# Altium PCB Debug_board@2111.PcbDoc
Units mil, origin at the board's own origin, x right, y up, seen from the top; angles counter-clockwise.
Board outline 1771.65 x 984.25 mil, 2 copper layers (Top Layer, Bottom Layer); 26 components, 28 nets, 104 pads, 124 vias.
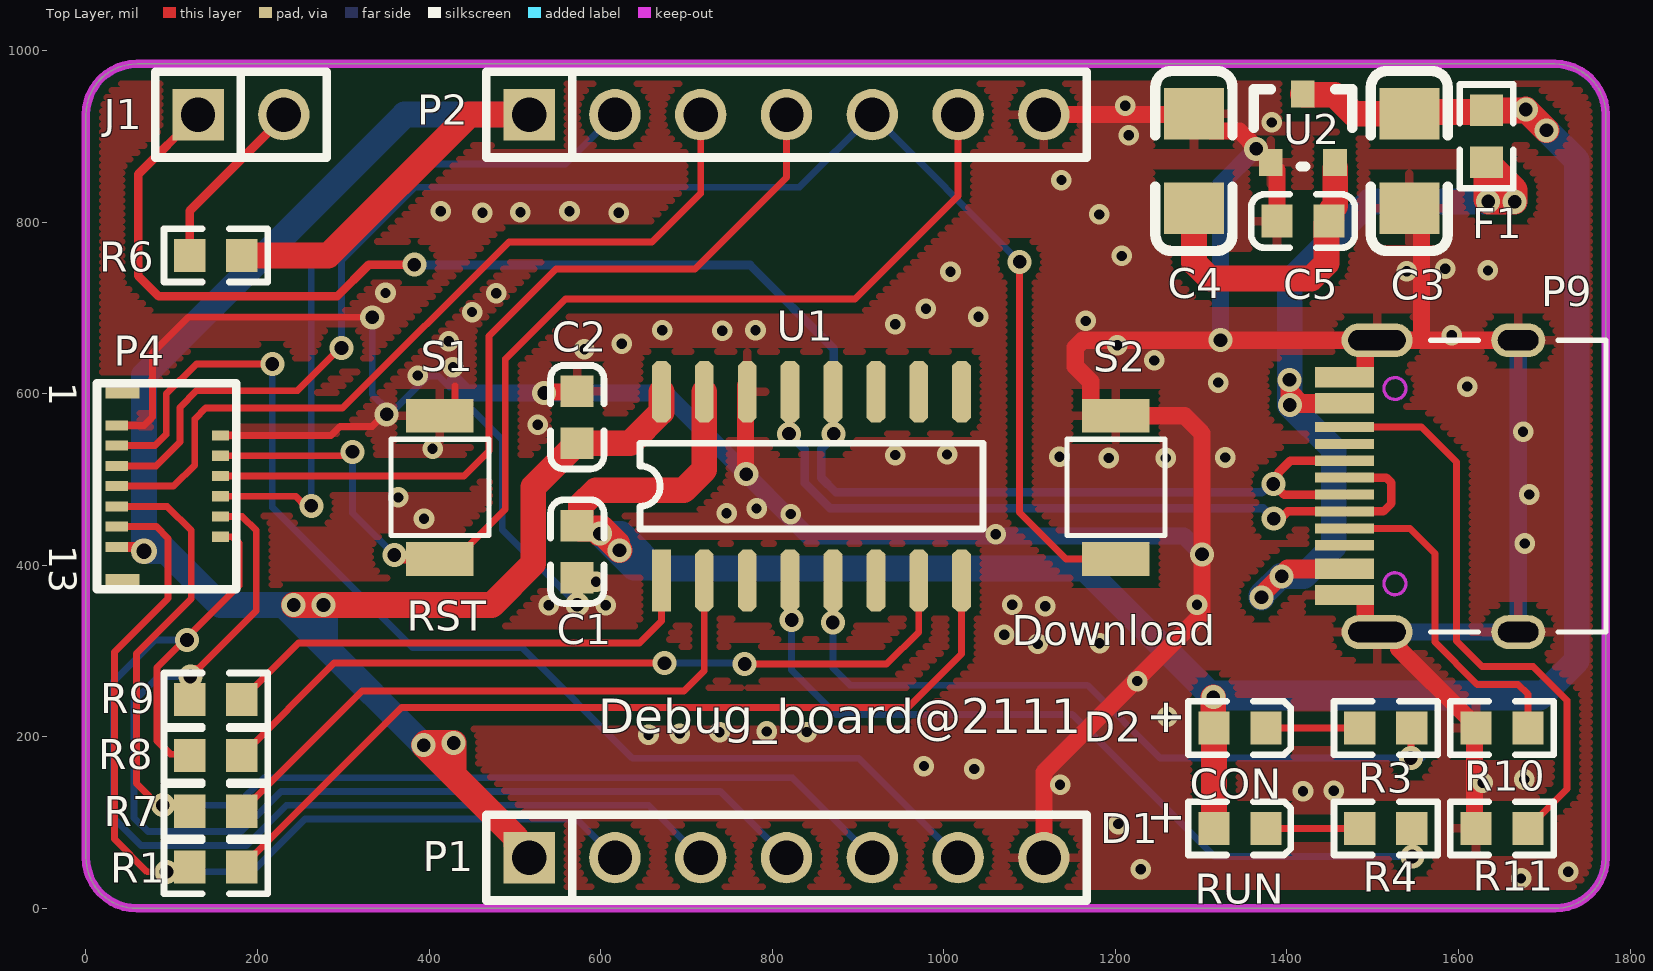
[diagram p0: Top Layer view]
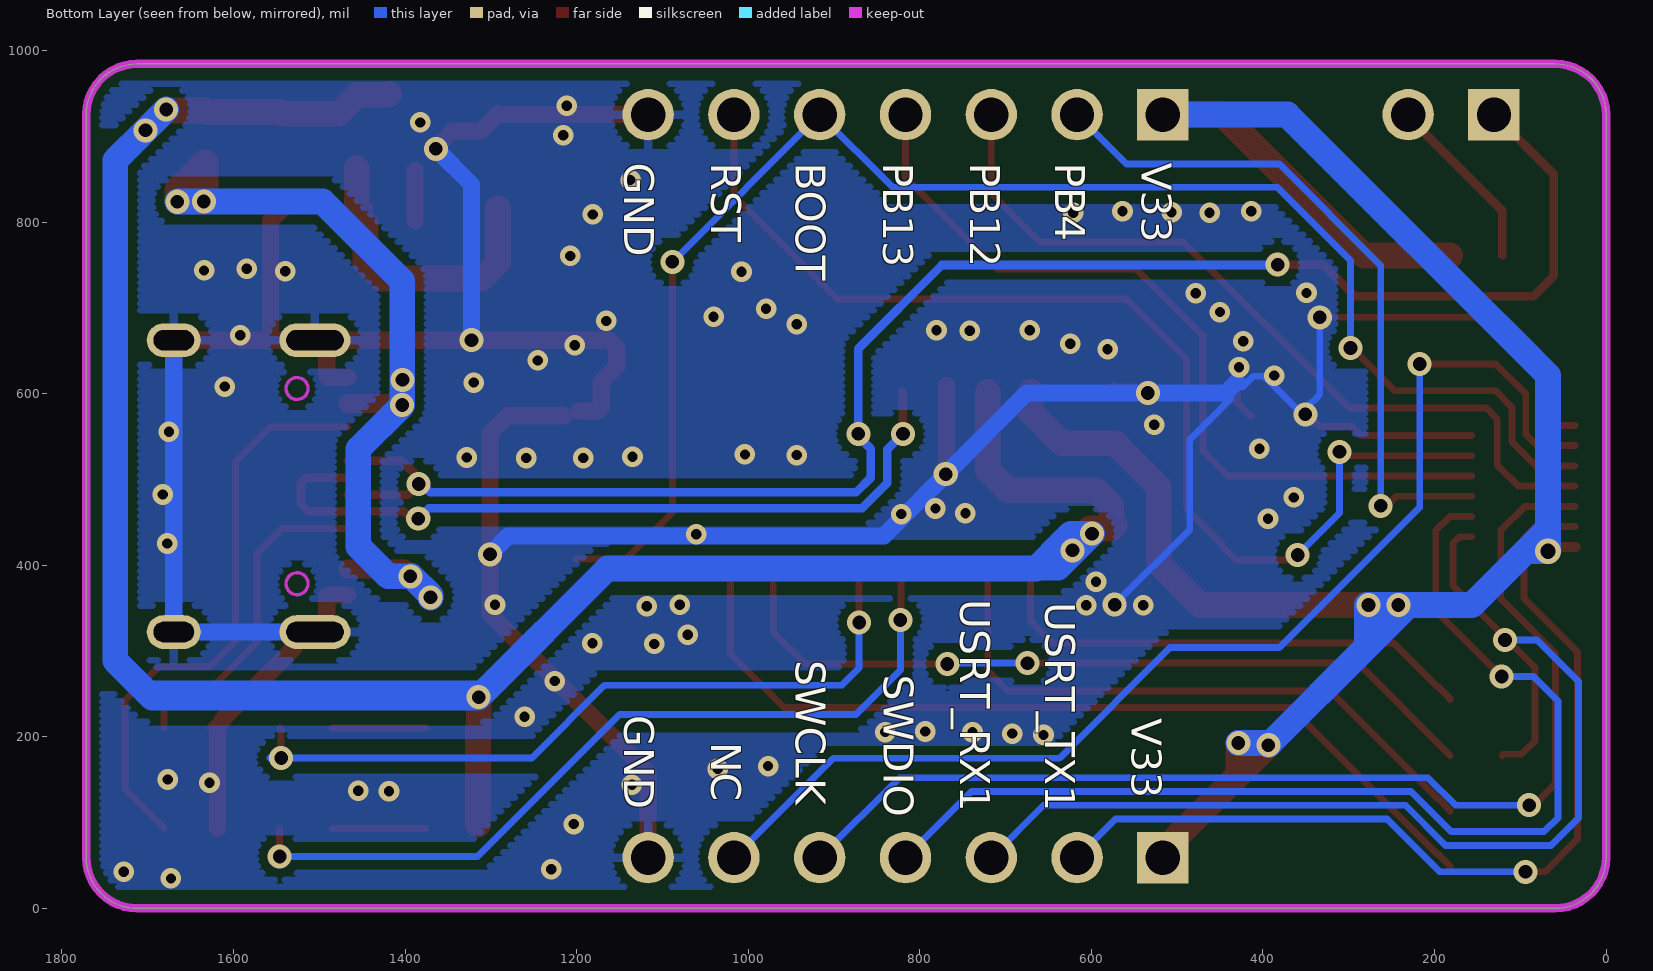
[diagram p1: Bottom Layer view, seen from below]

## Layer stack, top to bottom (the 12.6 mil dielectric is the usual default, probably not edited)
Top Solder: solder mask 0.4, Solder Resist, Dk 3.5
Top Layer: signal copper 1.4
Dielectric 1: dielectric 12.6, FR-4, Dk 4.8
Bottom Layer: signal copper 1.4
Bottom Solder: solder mask 0.4, Solder Resist, Dk 3.5

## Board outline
0,59.06 0,925.2 cw(c59.06,925.2) 59.06,984.25 1712.6,984.25 cw(c1712.6,925.2) 1771.65,925.2 1771.65,59.06 cw(c1712.6,59.06) 1712.6,0 59.06,0 cw(c59.06,59.06)

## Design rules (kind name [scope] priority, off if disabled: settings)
Clearance Clearance_2 [InComponent('P9')] p1: gap=6 ignorepadtopadclearanceinfootprint=FALSE
Clearance Clearance_1 [InPolygon] p2: gap=10 ignorepadtopadclearanceinfootprint=FALSE
Clearance [All] p3: gap=8 ignorepadtopadclearanceinfootprint=FALSE
ComponentClearance [All] p1 off: gap=10 collisioncheckmode=3 verticalgap=10 showdistances=FALSE
DiffPairsRouting [All] p1: maxlimit=10 minlimit=7 mostfreqgap=8 toplayer_minwidth=6 toplayer_maxwidth=15 toplayer_prefwidth=8 bottomlayer_minwidth=6 bottomlayer_maxwidth=15 bottomlayer_prefwidth=8 maxuncoupledlength=500
MinimumSolderMaskSliver [All] p1 off: minsoldermaskwidth=10
PolygonConnect PolygonConnect_1 [IsVia] p1: connectstyle=Direct reliefconductorwidth=10 reliefentries=4 polygonreliefangle="90 Angle" airgapwidth=10
PolygonConnect [All] p2: connectstyle=Relief reliefconductorwidth=10 reliefentries=4 polygonreliefangle="90 Angle" airgapwidth=10
RoutingVias [All] p1: holewidth=16 width=28 viastyle="Through Hole" minholewidth=12 minwidth=24 maxholewidth=28 maxwidth=50
SilkToSilkClearance [All] p1 off: silktosilkclearance=10
SilkToSolderMaskClearance [IsPad] p1 off: minsilkscreentomaskgap=10 clearancetoexposedcopper=TRUE
SolderMaskExpansion [All] p1: expansion=4 istentingtop=FALSE
Width [All] p1: maxlimit=100 minlimit=6 preferedwidth=10
25 further rules are at their usual default settings.

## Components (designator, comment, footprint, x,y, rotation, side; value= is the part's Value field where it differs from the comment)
C1 "0.1uF" 0603_C 572.65,446.13 r270 top
C2 "0.1uF" 0603_C 572.65,542.13 r90 top
C3 "10uF" 3216_C 1542.65,926.13 r90 top
C4 "10uF" 3216_C 1291.65,816.13 r270 top
C5 "0.1uF" 0603_C 1449.07,801.13 r180 top
D1 "RED" 0603+ 1315.02,93.13 r0 top
D2 "BLUE" 0603+ 1315.02,210.13 r0 top
F1 "500mA" 0603 1632.65,869.5 r90 top
J1 "Header 2" SIP2-2.54MM 130.65,925.2 r90 top
P1 "Header 7" SIP7-2.54mm 516.65,59.06 r90 top
P2 "Header 7" SIP7-2.54mm 516.65,925.2 r90 top
P4 "FPC连接器 13PIN_0.3mm" FFC/FPC-13(6+7)-P0.3 35.98,492.13 r270 top
P9 "TYPE-C" TYPE-C-Receptacle-2.0 1466.9,492.13 r90 top
R1 "270" 0603 121.07,48.05 r0 top
R3 "1K" 0603 1545.65,210.13 r180 top
R4 "1K" 0603 1545.65,93.13 r180 top
R6 "4.7K" 0603 121.07,761.04 r0 top
R7 "270" 0603 121.07,113.12 r0 top
R8 "270" 0603 121.07,178.2 r0 top
R9 "270" 0603 121.07,243.27 r0 top
R10 "NC(5.1K)" 0603 1681.08,210.13 r180 top
R11 "NC(5.1K)" 0603 1681.08,93.13 r180 top
S1 "RST" 贴片按键 412.65,407.13 r90 top
S2 "Download" 贴片按键 1200.65,407.13 r90 top
U1 "CH549G" SOP16 670.83,382.13 r0 top
U2 "CE6219" SOT-23 1381.25,869.6 r0 top

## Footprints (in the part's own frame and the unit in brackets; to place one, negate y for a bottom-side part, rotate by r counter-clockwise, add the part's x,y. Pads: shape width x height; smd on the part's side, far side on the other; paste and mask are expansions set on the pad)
0603 [mm]
  rect 0.93x0.98 smd: 1(0,0) 2(1.54,0)
  silkscreen extent -0.76,-0.79 2.3,0.79
0603+ [mm]
  rect 0.93x0.98 smd: 1(0,0) 2(1.54,0)
  silkscreen extent -0.76,-0.79 2.27,0.79
0603_C [mm]
  rect 0.93x0.98 smd: 1(0,0) 2(1.54,0)
  silkscreen extent -0.76,-0.79 2.31,0.79
3216_C [mil]
  rect 60x70 smd: 1(0,0) 2(-110,0)
  silkscreen extent -160,-45 50,45
FFC/FPC-13(6+7)-P0.3 [mm]
  rect 0.35x1 smd mask+0.102: 0(-2.775,0.165) 0(2.775,0.165)
  rect 0.3x0.67 smd mask+0.102: 1(-1.8,0) 3(-1.2,0) 5(-0.6,0) 7(0,0) 9(0.6,0) 11(1.2,0) 13(1.8,0)
  rect 0.3x0.5 smd mask+0.102: 2(-1.5,3.065) 4(-0.9,3.065) 6(-0.3,3.065) 8(0.3,3.065) 10(0.9,3.065) 12(1.5,3.065)
  silkscreen extent -3.05,-0.59 3.05,3.53
SIP2-2.54MM [mil]
  rect 60x60 hole 40: 1(0,0)
  round 60 hole 40: 2(0,-100)
  silkscreen extent -50,-150 50,50
SIP7-2.54mm [mil]
  rect 60x60 hole 40: 1(0,0)
  round 60 hole 40: 2(0,-100) 3(0,-200) 4(0,-300) 5(0,-400) 6(0,-500) 7(0,-600)
  silkscreen extent -50,-650 50,50
SOP16 [mil]
  rect 22x72 smd: 1(0,0)
  oct 22x72 smd: 2(50,0) 3(100,0) 4(150,0) 5(200,0) 6(250,0) 7(300,0) 8(350,0) 9(350,220) 10(300,220) 11(250,220) 12(200,220) 13(150,220) 14(100,220) 15(50,220) 16(0,220)
  silkscreen extent -25,60 375,160
SOT-23 [mm]
  rect 0.7x0.8 smd: 1(0,0) 2(1.9,0) 3(0.95,2.02)
  silkscreen extent -0.51,-0.13 2.41,2.16
TYPE-C-Receptacle-2.0 [mm]
  oval 1x1.6 hole 0.6 slot 1.2 at 90 deg: 0(-4.32,-5.15) 0(4.32,-5.15)
  oval 1x2.1 hole 0.6 slot 1.7 at 90 deg: 0(-4.32,-0.97) 0(4.32,-0.97)
  rect 0.6x1.75 smd: A1(-3.225,0) A4(-2.45,0) B1(3.225,0) B4(2.45,0)
  rect 0.3x1.75 smd: A5(-1.25,0) A6(-0.25,0) A7(0.25,0) A8(1.25,0) B5(1.75,0) B6(0.75,0) B7(-0.75,0) B8(-1.75,0)
  Keep-Out Layer circle w0.1: c-2.89,-1.5 r0.325
  Keep-Out Layer circle w0.1: c2.89,-1.5 r0.325
  silkscreen extent -4.32,-7.75 4.32,-2.55
贴片按键 [mm]
  rect 1x2 smd: 1(0,0) 2(4.242,0)
  silkscreen extent 0.69,-1.45 3.55,1.45

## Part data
C1 C2: library part C0603, "Capacitor"
C3 C4 C5: library part CAP, "Capacitor"
D1 D2: library part D0603, "Typical RED, GREEN, YELLOW, AMBER GaAs LED"
F1: library part FUSE1, "Fuse"
J1: "Header, 2-Pin"
P1 P2: "Header, 7-Pin"
P4: library part "Header 13", "Header, 13-Pin"
P9: library part TYPE-C1
R1 R3 R4 R6 R7 R8 R9: library part R0603, "Resistor"
R10 R11: library part Res2, "Resistor"
S1 S2: library part SW-PB, "Switch"
U1: "8bit MCS51 MCU with ADC & USB type-C host & device & dual UART & SPI"
U2: library part LM1117_3.3V

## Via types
v1: diameter 24, hole 12, Top Layer to Bottom Layer, tented both sides, 79 vias
v2: diameter 28, hole 16, Top Layer to Bottom Layer, tented both sides, 44 vias
v3: diameter 30, hole 18, Top Layer to Bottom Layer, tented both sides, 1 vias

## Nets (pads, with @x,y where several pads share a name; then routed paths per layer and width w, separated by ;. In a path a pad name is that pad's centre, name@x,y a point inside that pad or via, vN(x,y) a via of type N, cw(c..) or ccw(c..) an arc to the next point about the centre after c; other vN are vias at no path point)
3V3: C4.1 C5.1 U2.2 | length 348.6
  Top Layer w30: C4.1 1291.65,752.77 1310.34,734.08 1428.36,734.08 1446.12,751.83 1446.12,798.17 C5.1 1452.37,804.43 1452.37,814.6 1456.37,818.6 U2.2@1456.37,863.26
5V: C1.1 C3.1 D1.1 D2.1 F1.2 U1.15 U2.3 | length 3194.1
  Top Layer w30: v2(599.33,436.63) 602.68,436.63 v2@619.2,420.1 ; v2(622.02,417.29) v2@619.2,420.1 ; U1.15 720.83,511.14 697.02,487.33 594.61,487.33 576.94,469.67 576.94,449.43 C1.1@573.64,446.13 ; v2(1314.14,246.11) 1314.14,211.01 D2.1 D1.1@1315.02,97.45 ; U2.3 1419.4,948.38 1455.4,948.38 1477.65,926.13 C3.1 1544.65,928.13 1630.65,928.13 F1.2 v2@1677.39,930.13 ; v2(1678.5,931.24) v2@1677.39,930.13 ; v2(1702.56,906.91) 1679.35,930.13 v2@1677.39,930.13 ; C1.1@573.64,446.13 C1.1@576.94,442.82 ; C1.1@573.64,446.13 C1.1 575.96,442.82 C1.1@576.94,442.82 ; C1.1@576.94,442.82 601.63,442.82 619.2,425.25 v2@619.2,420.1
  Bottom Layer w30: 664.34,396.14 1164.11,396.14 1309.54,250.71 1314.14,250.71 1699.93,250.71 ; v2(1314.14,246.11) 1314.76,245.49 1694.71,245.49 1699.93,250.71 ; v2(1678.5,931.24) 1702.7,907.04 1737.76,871.97 1737.76,288.54 1699.93,250.71 ; v2(599.33,436.63) 620.35,415.62 638.69,397.27 663.2,397.27 632.6,427.87 623.84,436.63 v2(599.33,436.63)
5V_USB: F1.1 P9.A4 P9.B4 | length 1125.6
  Top Layer w22: v2(1370.27,362.42) 1370.27,365.2 v2@1400.74,395.67 ; v2(1393.86,387.02) 1393.86,388.79 v2@1400.74,395.67 ; v2(1403.05,616.08) 1403.23,615.89 1403.23,601.34 ; 1427.42,588.28 v2@1416.29,588.28 ; P9.A4 v2@1400.74,395.67 ; P9.B4@1466.9,588.28 v2@1416.29,588.28 ; 1403.23,601.34 1403.23,586.78 v2(1403.42,586.59) 1405.05,586.59 1406.74,588.28 v2@1416.29,588.28 ; 1403.23,601.34 v2@1416.29,588.28
  Top Layer w30: v2@1632.65,825.82 F1.1 1633.64,869.5 1665.52,837.61 v2(1665.52,823.61) 1665.33,823.81 v2(1634.66,823.81) v2@1632.65,825.82
  Bottom Layer w30: v2(1370.27,362.42) 1370.27,364.94 v2@1393.1,387.78 ; v2(1393.86,387.02) 1419.77,387.02 1454.6,421.85 1454.6,535.41 v2(1403.42,586.59) 1403.42,616.08 1403.42,731.26 1495.97,823.81 v2(1634.66,823.81) 1665.33,823.81 v2(1665.52,823.61)
BOOT: P2.5 P4.5 S2.1 | length 1803.5
  Top Layer w8: P4.5 81.94,515.75 109.62,543.43 109.62,583.86 129.07,603.31 246.41,603.31 296.2,653.1 v2(298.01,653.1) ; v2(1088.44,753.65) 1088.44,461.32 1142.63,407.13 S2.1
  Bottom Layer w8: v2(298.01,653.1) 298.01,755.12 383.44,840.55 832.01,840.55 P2.5 v2@1088.32,753.53
D_SWCLK: R7.2 U1.2 | length 712.8
  Top Layer w8: R7.2 181.7,114.11 196.01,128.42 196.99,128.42 321.97,253.39 697.3,253.39 720.83,276.91 U1.2
D_SWDIO: R9.2 U1.1 | length 574.9
  Top Layer w8: R9.2 181.7,244.26 196.01,258.57 196.99,258.57 247.75,309.32 645.34,309.32 670.83,334.8 U1.1
GND: C1.2 C2.2 C3.2 C4.2 C5.2 P1.7 P2.7 P4.1 P4.2 P9.0 P9.A1 P9.B1 R10.2 R11.2 S1.2 S2.2 U1.14 U2.1 | length 5194.2
  Top Layer w8: P4.1 67.95,562.99 77.43,572.48 77.43,647.21 119.18,688.96 v2(333.73,688.96) ; P4.2 285.74,551.18 296.12,561.56 333.68,561.56 347.88,575.77 v2(350.58,575.77) ; S1.2 414.46,574.13 430.15,589.81 430.15,609.13
  Top Layer w20: v2(534.23,600.56) 535.33,601.66 571.56,601.66 C2.2 ; U1.14@768.84,609.25 768.84,506.93 v2(769.73,506.03) ; P1.7 1116.65,158.35 1301.09,342.79 v2(1301.09,412.68) 1301.09,553.6 1280.57,574.13 S2.2@1214.81,574.13 ; P2.7 1290.72,925.2 C4.2 1311.65,906.13 1344.72,906.13 v2@1364.84,886.01 ; S2.2@1197.87,579.63 1175.46,579.63 1171.28,583.81 1171.28,613.81 1153.23,631.86 1153.23,653.42 1162.02,662.2 v2(1322.6,662.2) 1505.09,662.2 P9.0@1669.65,662.2 ; C5.2 U2.1@1388.44,860.44 ; P9.A1 1489.54,365.16 1491.35,363.35 1491.35,330.83 1500.13,322.05 P9.0@1505.09,322.05 ; P9.B1 1489.54,619.09 1491.35,620.91 1491.35,653.26 1486.88,657.72 P9.0@1484.2,657.72 ; P9.0@1510.89,322.05 1521.5,322.05 1530.45,313.1 1530.45,302.49 1612.14,220.8 1612.14,218.43 R10.2 ; C3.2 1556.9,801.88 1556.9,662.21 ; R11.2@1618.65,93.13 R10.2@1618.65,208.13
  Bottom Layer w8: v2(333.73,688.96) 333.73,599.17 350.58,582.32 v2(350.58,575.77) 354.39,575.77 356.42,577.8 393.13,614.51 398.82,620.2 411.32,620.2 423.79,607.74 ; 437.32,594.2 485.25,546.27 485.25,441.48 v2(572.79,353.95)
  Bottom Layer w20: 430.15,614.09 438.4,605.84 443.68,600.56 v2(534.23,600.56) 675.2,600.56 v2(769.73,506.03) v1@818.94,456.83 ; v1@820.32,458.21 821.85,458.21 822.39,457.67 822.39,453.37 841.66,434.11 1279.67,434.11 v2(1301.09,412.68) ; v2(1322.6,662.2) 1322.6,843.77 v2(1364.15,885.32) ; P9.0@1505.09,322.05 1669.65,322.05 P9.0@1669.65,662.2
  other v1: 1673,34.82 1727.96,42.45 1229.44,45.51 1203.48,98.19 1418.77,136.36 1454.65,137.12 1135.54,143.99 1627.95,146.28 1676.81,150.1 1035.53,162.31 976.86,165.74 655.78,202.1 692.23,203.67 738.55,205.06 840.37,205.42 793.73,206.08 1260.68,223.41 1225.52,264.84 1109.38,308.16 1181.57,308.79 1070.46,318.83 1118.17,352.11 539.36,353.19 605.94,353.19 1079.87,353.99 1295.2,353.99 594.61,380.73 1677.11,425.27 1060.66,436.11 394.08,454.02 821.62,459.52 746.8,460.61 781.75,466.07 364.17,478.95 1682.54,482.32 1192.14,524.86 1258.76,524.86 1328.04,525.53 1134.85,526.19 943.48,528.31 1003.82,529.1 404.09,535.61 1675.3,555.66 526.75,563.79 1610.1,608.18 1319.98,612.86 386.67,620.97 427.88,630.8 1245.37,638.65 581.07,651.7 1202.38,656.21 624.66,658.13 422.8,660.94 1591.99,667.94 741.87,673.14 671.83,673.86 780.47,673.86 943.48,680.77 1165.43,684.68 1040.35,689.5 450.08,695 979.21,699.03 349.24,717.35 478.4,716.84 1007.79,741.91 1539.65,742.67 1634.34,743.57 1584.74,745.38 1207.54,760.48 1181.25,808.85 462.16,810.84 506.46,811.38 620.98,810.84 413.54,812.46 563.72,812.46 1137.11,848.91 1215.58,901.22 1382.24,916.08 1211.49,935.55
LED_CON: R3.1 U1.5 | length 868.3
  Top Layer w8: v2(870.65,333.13) 870.83,333.3 U1.5 ; v2(1544.47,175.15) 1544.47,208.94 R3.1
  Bottom Layer w8: v2(870.65,333.13) 870.65,279.9 890.51,260.04 1167.26,260.04 1252.15,175.15 v2(1544.47,175.15) v2@1557.79,175.15
LED_RUN: R4.1 U1.4 | length 951.5
  Top Layer w8: U1.4 821.72,381.23 821.72,336.99 v2(822.62,336.09) ; R4.1 1546.19,92.59 v2(1546.19,60.45)
  Bottom Layer w8: v2(822.62,336.09) 822.62,277.88 874.47,226.03 1149.83,226.03 1315.42,60.45 v2(1546.19,60.45)
NC: P1.6 P4.3 | length 1384
  Top Layer w8: P4.3 80.57,539.37 93.55,552.35 93.55,599.37 128.74,634.56 v2(217.23,634.56)
  Bottom Layer w8: v2(217.23,634.56) 217.23,467.32 380.59,303.96 508.21,303.96 637.34,174.83 900.88,174.83 P1.6
NetD1_2: D1.2 R4.2 | length 109.4
  Top Layer w8: D1.2 R4.2
NetD2_2: D2.2 R3.2 | length 109.4
  Top Layer w8: D2.2 R3.2
NetJ1_2: J1.2 R6.1 | length 209.5
  Top Layer w10: R6.1 121.07,813.2 144.92,837.05 230.65,922.78 J1.2
NetP9_A5: P9.A5 R10.1 | length 394.2
  Top Layer w8: P9.A5 1543.31,442.91 1572.54,413.68 1572.54,310.32 1621.83,261.03 1669.56,261.03 1681.08,249.52 R10.1
NetP9_B5: P9.B5 R11.1 | length 682
  Top Layer w8: P9.B5 1556.98,561.02 1597.6,520.41 1597.6,311.72 1627.58,281.74 1687.14,281.74 1726.43,242.45 1726.43,139.2 1695.65,108.42 1695.38,108.42 1681.08,94.11 R11.1
PB4: P2.2 P4.8 | length 817.7
  Top Layer w8: P4.8 244.38,480.32 255.57,469.13 v2(262.65,469.13)
  Bottom Layer w8: v2(262.65,469.13) 262.65,749.43 380.78,867.56 559.02,867.56 P2.2
PB12: P2.3 P4.7 | length 945.1
  Top Layer w8: P4.7 102.07,492.13 126.89,516.95 126.89,570.34 139.57,583.01 299.11,583.01 492.94,776.85 660.06,776.85 716.65,833.45 P2.3
PB13: P2.4 P4.6 | length 956
  Top Layer w8: P4.6 329.41,503.94 440.74,503.94 457.93,521.13 469.86,533.05 469.86,667.04 547.99,745.18 710.06,745.18 816.65,851.77 P2.4
RST: P2.6 P4.4 S1.1 | length 1329.8
  Top Layer w8: P4.4 306.09,527.56 v2(310.65,532.13) ; v2(359.5,411.77) 365.07,406.19 431.41,406.19 448.02,422.81 448.02,424.59 488.79,465.36 488.79,640.15 558.96,710.32 896.48,710.32 1016.65,830.49 P2.6
  Bottom Layer w8: v2(310.65,532.13) 310.65,460.61 v2(359.5,411.77)
SWCLK: P1.5 P4.9 R7.1 | length 1342.1
  Top Layer w8: P4.9 94.73,468.5 122.78,440.46 122.78,361.18 58.79,297.2 58.79,145.25 v2@89.36,114.69
  Bottom Layer w8: v2(89.65,120.13) 175.59,120.13 207.56,152.1 823.61,152.1 P1.5
SWDIO: P1.4 P4.10 R9.1 | length 1279.7
  Top Layer w8: v2@121.07,279.64 131.17,279.64 198.52,346.99 198.52,440.33 182.16,456.69 P4.10
  Bottom Layer w8: v2(121.65,270.13) 84.36,270.13 56.03,241.79 56.03,105.43 72.17,89.29 180.49,89.29 227.3,136.1 739.61,136.1 P1.4
UART0_RX: R8.2 U1.7 | length 909.4
  Top Layer w8: R8.2 289.24,285.73 v2(674.41,285.73) ; v2(767.87,284.84) 933.43,284.84 970.83,322.24 U1.7
  Bottom Layer w8: v2(674.41,285.73) 766.98,285.73 v2(767.87,284.84)
UART0_TX: R1.2 U1.8 | length 1028.3
  Top Layer w8: R1.2 181.7,49.03 196.01,63.34 196.99,63.34 367.67,234.01 958.38,234.01 1020.83,296.46 U1.8
UART_RX1: P1.3 P4.12 R8.1 | length 1347.3
  Top Layer w8: R8.1 119.65,179.62 98.28,179.62 82.81,195.09 82.81,280.51 178.3,376.01 178.3,425.82 171.06,433.07 P4.12
  Bottom Layer w8: v2(117.92,312.64) 80.63,312.64 32.24,264.24 32.24,105.2 64.14,73.29 187.12,73.29 233.93,120.1 655.61,120.1 P1.3
UART_TX1: P1.2 P4.11 R1.1 | length 1085.1
  Top Layer w8: P4.11 82.1,444.88 95.85,431.13 95.85,361.33 33.44,298.93 33.44,80.56 71.44,42.56 v2(93.9,42.56)
  Bottom Layer w8: v2(93.9,42.56) 193.72,42.56 255.26,104.1 571.61,104.1 P1.2
USB_N: P9.A7 P9.B7 U1.13 | length 909.4
  Top Layer w10: v2(819.65,553.13) 819.65,600.95 U1.13 ; v2@1380.06,453.43 1380.75,454.13 v2(1384.65,454.13) 1392.44,454.13 1400.91,462.6 P9.B7 1512.5,462.6 1521.86,471.96 1521.86,496.11 1516,501.97 P9.A7
  Bottom Layer w10: v2(819.65,553.13) 837.94,534.84 837.94,495.7 867.07,466.57 1372.21,466.57 v2(1384.65,454.13)
USB_P: J1.1 P9.A6 P9.B6 U1.12 | length 1973.5
  Top Layer w10: J1.1 61.06,855.6 61.06,737.15 84.91,713.31 292.73,713.31 329.67,750.25 v2(382.84,750.25) ; v2(1384.1,494.53) 1384.1,499.4 1389.86,505.16 1389.86,507.7 1403.82,521.65 P9.B6 ; v2@1390.44,496.49 1390.44,488.18 1396.79,481.84 1466.45,481.84 P9.A6
  Bottom Layer w10: v2@382.84,749.91 774.06,749.91 871.65,652.32 871.65,550.11 857.19,535.65 857.19,501.9 874.34,484.76 1370.71,484.76 1380.47,494.53 v2(1384.1,494.53)
  other v2: 871.65,553.13
V33: C2.1 P1.1 P2.1 P4.13 R6.2 U1.16 | length 2847.9
  Top Layer w12: P4.13 57.11,421.26 62.24,416.13 v3(67.65,416.13)
  Top Layer w30: R6.2 282.5,761.04 446.65,925.2 P2.1 ; v2(242.15,353.41) v2(276.9,353.41) ; v2@278.9,353.41 473.04,353.41 521.49,401.86 521.49,491.16 568.36,538.04 568.36,538.82 571.67,542.13 634.34,542.13 670.83,578.62 U1.16 ; 438.73,145.05 428.66,155.12 ; P1.1 501.65,74.06 501.65,82.13 428.66,155.12 ; 428.66,155.12 v2(393.65,190.13) 396.12,192.59 v2(428.66,192.59) 428.66,155.12
  Bottom Layer w30: 85.69,424.15 156.42,353.41 ; v2(393.65,190.13) v2@391.19,192.59 ; v2(428.66,192.59) v2@391.19,192.59 ; P2.1 371.45,925.2 67.65,621.4 67.65,442.18 ; v3(67.65,416.13) 67.65,442.18 ; v3(67.65,416.13) 93.71,416.13 ; v3(67.65,416.13) 71.36,419.83 71.36,438.47 ; 67.65,442.18 71.36,438.47 ; 67.65,442.18 71.36,438.47 ; 71.36,438.47 93.71,416.13 ; 93.71,416.13 156.42,353.41 ; 156.42,353.41 v2@230.37,353.41 ; v2@230.37,353.41 v2@244.15,339.63 ; v2@230.37,353.41 v2@244.15,353.41 ; v2@244.15,339.63 261.52,322.26 ; v2@244.15,339.63 v2@244.15,353.41 ; v2@244.15,353.41 261.52,353.41 ; 261.52,322.26 278.9,304.88 ; 261.52,322.26 261.52,353.41 ; 261.52,353.41 278.9,353.41 278.9,304.88 ; 278.9,304.88 v2@391.19,192.59
pads on no net: P4.0 P9.A8 P9.B8 U1.3 U1.6 U1.9 U1.10 U1.11

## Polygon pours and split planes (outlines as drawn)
GND on Top Layer "GND" (hatched Horizontal grid 8 track 8, remove dead copper, pour order 4): 0,925.2 0,59.06 ccw(c59.06,59.06) 59.06,0 1712.6,0 ccw(c1712.6,59.06) 1771.65,59.06 1771.65,925.2 ccw(c1712.6,925.2) 1712.6,984.25 59.06,984.25 ccw(c59.06,925.2)
GND on Bottom Layer "GND" (hatched Horizontal grid 8 track 8, remove dead copper, pour order 3): 0,925.2 0,59.06 ccw(c59.06,59.06) 59.06,0 1712.6,0 ccw(c1712.6,59.06) 1771.65,59.06 1771.65,925.2 ccw(c1712.6,925.2) 1712.6,984.25 59.06,984.25 ccw(c59.06,925.2)

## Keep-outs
Keep-Out Layer:
  the board outline again, w10

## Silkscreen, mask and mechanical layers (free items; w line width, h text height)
Top Overlay:
  text "Debug_board@2111" at 596.93,203.86 h40
  text "CON" at 1286.64,127.7 h35
  text "RUN" at 1292.38,5.36 h35
Bottom Overlay:
  text "V33" at 541.46,869.2 h35 r90
  text "PB4" at 642.23,869.2 h35 r90
  text "PB12" at 741.29,869.2 h35 r90
  text "PB13" at 842.52,869.2 h35 r90
  text "BOOT" at 944.49,869.2 h35 r90
  text "RST" at 1043.26,869.2 h35 r90
  text "GND" at 1144.53,869.2 h35 r90
  text "USRT_RX1" at 752.95,360.22 h35 r90
  text "USRT_TX1" at 653.9,356.56 h35 r90
  text "SWCLK" at 944.49,289.07 h35 r90
  text "SWDIO" at 842.19,272.24 h35 r90
  text "GND" at 1144.53,224.92 h35 r90
  text "V33" at 553.13,221.25 h35 r90
  text "NC" at 1043.26,193.59 h35 r90
Mechanical 1:
  the board outline again, w10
